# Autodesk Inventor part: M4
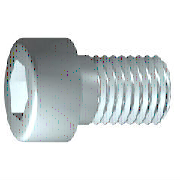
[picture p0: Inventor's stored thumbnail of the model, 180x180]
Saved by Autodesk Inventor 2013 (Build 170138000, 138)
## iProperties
IsCustomPart: 0
Company: 한국ATC센터
Created: 2014-10
Part Number: M4
Material: Steel, Mild
Description: 6각머리 태핑 나사
Document SubType Name: Modeling
Standard: KS B 1003
Designer: KYOUNG IL JANG
Standards Organization: KS
Language: ko-KR
Size Designation: M 4 x 10
Categories: <MemberInstance><Categories><Category DisplayName="조임쇠" InternalName="e4da775c-781d-43d5-af7c-5136215cf5a6" Mnemonic="FSTN"><Category DisplayName="볼트" InternalN
Density: 7.86 g/cm^3
Mass: 2.0371 g
Surface Area: 3.0572 cm^2
Volume: 0.259174 cm^3
Author: KYOUNG IL JANG
Revision Number: 1
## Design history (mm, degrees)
sketch "스케치1"
  geometry: L1 (-1, 0)-(10, 0); L2 (10, 0)-(10, 2); L3 (10, 2)-(1.75, 2); L4 (1.75, 2)-(1.32, 2); L5 (1.32, 2)-(0, 2); L6 (0, 2)-(0, 3.5); L7 (0, 3.5)-(-4, 3.5); L8 (-4, 3.5)-(-4, 1.732); L9 (-4, 1.732)-(-2, 1.732); L10 (-2, 1.732)-(-1, 0); L11 (-6.8, 0)-(12.8, 0) reference; L12 (0, -0.7)-(0, 4.2) reference; L13 (1.75, 2)-(0, 2)
  constraints: 22 end point, 6 parallel, 2 collinear, 2 perpendicular, 1 horizontal, 1 point on line
  dimensions: "d1" = 8.25 distance from line of L3.end L2 (= GEL); "d2" = 0.42952 distance of L4.end L3.end (computed from GAL); "d3" = 4 distance between parallel lines of L8 L6 (= KOH); "d4" = 2 distance of L8.end L9.end (= INTI); "d5" = 60 deg angle of L10 L1; "d6" = 4 diameter of L3 L1 (= GD); "d7" = 4 diameter of L5 L1 (= BDM); "d8" = 3.4641 diameter of L9 L1 (= 1.1547 x SW); "d9" = 7 diameter of L7 L1 (= KOD); "d26" = 10 distance between parallel lines of L12 L2 (= NLG)
revolve "본체" sketch "스케치1" stored, may be unused: angle "d10" = 90 deg
sketch "스케치2"
  geometry: L1 (0, -4.9)-(0, 4.9) reference; L2 (-4.9, 0)-(4.9, 0) reference; L3 (1.732, 0)-(0.866, -1.5); L4 (0.866, -1.5)-(-0.866, -1.5); L5 (-0.866, -1.5)-(-1.732, 0); L6 (-1.732, 0)-(-0.866, 1.5); L7 (-0.866, 1.5)-(0.866, 1.5); L8 (0.866, 1.5)-(1.732, 0); 2 further points
  constraints: 12 end point, 1 coincident, 1 horizontal alignment, 1 point on line, 12 other
extrude "슬롯" join sketch "스케치2" stored distance "d11" = 10; taper "d12" = 0 deg
workplane "Work Plane1"
fillet "Fillet2" dims "d30" = 0.1 (= R)
body "Solid1"
fillet "모깎기1" dims "d17" = 0.4 (= RR)
feature "스레드" dims "d13" = 8.25 (= GEL), "d14" = 0
chamfer "모따기1" distance "d15" = 0.42941 (= -0.5 x SPD + 0.5 x GD); stored, may be unused: second distance "d16" = 0.42941 (= GUL), angle "d27" = 45 deg
other parameters: "GD" = 4 (= NND) [user parameter; used in 2 equation terms], "NLG" = 10 [user parameter; used in 1 equation term], "GEL" = 8.25 [user parameter; used in 2 equation terms], "KOD" = 7 [user parameter; used in 1 equation term], "KOH" = 4 [user parameter; used in 1 equation term], "INTI" = 2 [user parameter; used in 1 equation term], "GAL" = 0.42941 (= 0.61345 x PTC) [user parameter; used in 1 equation term], "GUL" = 0.42941 (= 0.61345 x PTC) [user parameter; used in 1 equation term], "BDM" = 4 (= NND) [user parameter; used in 1 equation term], "SW" = 3 [user parameter; used in 2 equation terms], "RR" = 0.4 [user parameter; used in 1 equation term], "SPD" = 3.14117 (= NND - 1.2269 x PTC) [user parameter; used in 1 equation term], "d19" = 0, "d28" = 0, "d29" = 0, "R" = 0.1 [user parameter; used in 1 equation term], "PHH" = 0.2 [user parameter], "GD1" = 3.14117 (= THREADDIA - 1.2269 x PTC) [user parameter], "THREADDIA" = 4 [user parameter; used in 1 equation term], "FAWI" = 45 deg [user parameter], "TPU" = 14.28571 (computed from PTC) [user parameter], "PTC" = 0.7 [user parameter; used in 5 equation terms], "NND" = 4 [user parameter; used in 3 equation terms], "TOA" = 30 deg [user parameter], "E0" = 3.465 (= 1.155 x SW) [user parameter]
